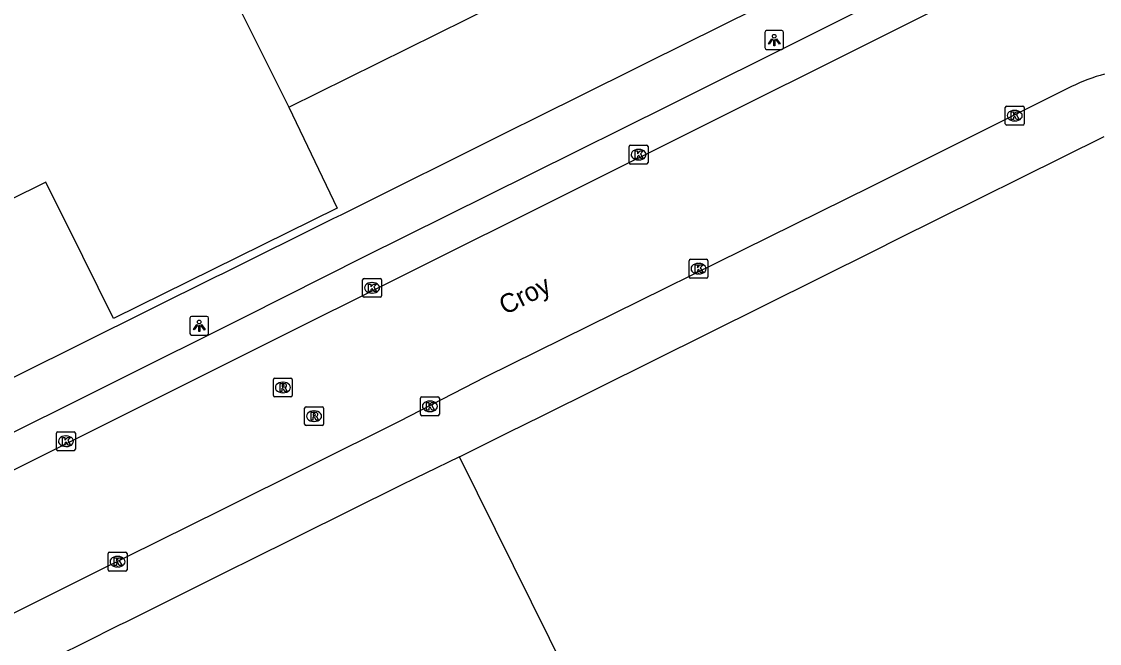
# Model space of a CAD drawing. Extents: x 157793 to 159380, y 380882 to 382313.
# Drawn here: x 157996.8 to 158053.9, y 381465.3 to 381498.3 of the extents above; entities that cross this region are included whole.
import ezdxf

# ---------------------------------------------------------------- set-up
doc = ezdxf.new("R2010")
doc.units = 0
for name, color, linetype in [('IMGEO_Kolk', 7, 'Continuous'), ('IMGEO_Lichtpunt', 7, 'Continuous'), ('IMGEO_Openbare_ruimte_label', 7, 'Continuous'), ('IMGEO_Pand', 7, 'Continuous'), ('IMGEO_Rijbaan_lokaal_gesloten', 7, 'Continuous'), ('IMGEO_Rioolput', 7, 'Continuous'), ('IMGEO_Voetpad_open', 7, 'Continuous')]:
    doc.layers.add(name, color=color, linetype=linetype)

msp = doc.modelspace()

# ---------------------------------------------------------------- linework, layer by layer
at = {"layer": 'IMGEO_Kolk'}
for p, q in [((158049.015, 381493.811), (158049.867, 381493.811)), ((158048.94, 381492.885), (158048.94, 381493.737)), ((158049.428, 381493.591), (158049.453, 381493.591)), ((158049.941, 381493.737), (158049.941, 381492.885)), ((158049.867, 381492.811), (158049.015, 381492.811)), ((158049.451, 381493.031), (158049.426, 381493.031)), ((158028.989, 381490.818), (158028.989, 381491.67)), ((158029.064, 381491.744), (158029.916, 381491.744)), ((158029.477, 381491.524), (158029.502, 381491.524)), ((158029.99, 381491.67), (158029.99, 381490.818)), ((158029.5, 381490.964), (158029.475, 381490.964)), ((158029.916, 381490.744), (158029.064, 381490.744)), ((158032.168, 381484.765), (158032.168, 381485.617)), ((158032.243, 381485.691), (158033.095, 381485.691)), ((158032.656, 381485.471), (158032.681, 381485.471)), ((158033.169, 381485.617), (158033.169, 381484.765)), ((158014.921, 381484.676), (158015.773, 381484.676)), ((158033.095, 381484.691), (158032.243, 381484.691)), ((158032.679, 381484.911), (158032.654, 381484.911)), ((158014.846, 381483.75), (158014.846, 381484.602)), ((158015.334, 381484.456), (158015.359, 381484.456)), ((158015.847, 381484.602), (158015.847, 381483.75)), ((158015.773, 381483.676), (158014.921, 381483.676)), ((158015.357, 381483.896), (158015.332, 381483.896)), ((158017.993, 381478.394), (158018.845, 381478.394)), ((158017.918, 381477.468), (158017.918, 381478.32)), ((158018.406, 381478.174), (158018.431, 381478.174)), ((158018.919, 381478.32), (158018.919, 381477.468)), ((158018.845, 381477.394), (158017.993, 381477.394)), ((158018.429, 381477.614), (158018.404, 381477.614)), ((157998.608, 381475.613), (157998.608, 381476.465)), ((157998.683, 381476.539), (157999.535, 381476.539)), ((157999.096, 381476.319), (157999.121, 381476.319)), ((157999.609, 381476.465), (157999.609, 381475.613)), ((157999.535, 381475.539), (157998.683, 381475.539)), ((157999.119, 381475.759), (157999.094, 381475.759)), ((158001.346, 381469.226), (158001.346, 381470.078)), ((158001.421, 381470.152), (158002.273, 381470.152)), ((158001.834, 381469.932), (158001.859, 381469.932)), ((158002.347, 381470.078), (158002.347, 381469.226)), ((158001.857, 381469.372), (158001.832, 381469.372)), ((158002.273, 381469.152), (158001.421, 381469.152))]:
    msp.add_line(p, q, dxfattribs=at)
for points in [[(158049.015, 381493.811), (158049.867, 381493.811)], [(158048.94, 381492.885), (158048.94, 381493.737)], [(158049.261, 381493.511), (158049.384, 381493.511), (158049.384, 381493.36), (158049.514, 381493.511), (158049.678, 381493.511), (158049.532, 381493.36), (158049.685, 381493.111), (158049.533, 381493.111), (158049.448, 381493.275), (158049.384, 381493.208), (158049.384, 381493.111), (158049.261, 381493.111), (158049.261, 381493.511)], [(158049.941, 381493.737), (158049.941, 381492.885)], [(158049.867, 381492.811), (158049.015, 381492.811)], [(158028.989, 381490.818), (158028.989, 381491.67)], [(158029.064, 381491.744), (158029.916, 381491.744)], [(158029.99, 381491.67), (158029.99, 381490.818)], [(158029.31, 381491.444), (158029.433, 381491.444), (158029.433, 381491.293), (158029.563, 381491.444), (158029.727, 381491.444), (158029.581, 381491.293), (158029.734, 381491.044), (158029.582, 381491.044), (158029.497, 381491.208), (158029.433, 381491.141), (158029.433, 381491.044), (158029.31, 381491.044), (158029.31, 381491.444)], [(158029.916, 381490.744), (158029.064, 381490.744)], [(158032.168, 381484.765), (158032.168, 381485.617)], [(158032.243, 381485.691), (158033.095, 381485.691)], [(158032.489, 381485.391), (158032.612, 381485.391), (158032.612, 381485.24), (158032.742, 381485.391), (158032.906, 381485.391), (158032.76, 381485.24), (158032.913, 381484.991), (158032.761, 381484.991), (158032.676, 381485.155), (158032.612, 381485.088), (158032.612, 381484.991), (158032.489, 381484.991), (158032.489, 381485.391)], [(158033.169, 381485.617), (158033.169, 381484.765)], [(158014.921, 381484.676), (158015.773, 381484.676)], [(158033.095, 381484.691), (158032.243, 381484.691)], [(158014.846, 381483.75), (158014.846, 381484.602)], [(158015.167, 381484.376), (158015.29, 381484.376), (158015.29, 381484.225), (158015.42, 381484.376), (158015.584, 381484.376), (158015.438, 381484.225), (158015.591, 381483.976), (158015.439, 381483.976), (158015.354, 381484.14), (158015.29, 381484.073), (158015.29, 381483.976), (158015.167, 381483.976), (158015.167, 381484.376)], [(158015.847, 381484.602), (158015.847, 381483.75)], [(158015.773, 381483.676), (158014.921, 381483.676)], [(158017.993, 381478.394), (158018.845, 381478.394)], [(158017.918, 381477.468), (158017.918, 381478.32)], [(158018.239, 381478.094), (158018.362, 381478.094), (158018.362, 381477.943), (158018.492, 381478.094), (158018.656, 381478.094), (158018.51, 381477.943), (158018.663, 381477.694), (158018.511, 381477.694), (158018.426, 381477.858), (158018.362, 381477.791), (158018.362, 381477.694), (158018.239, 381477.694), (158018.239, 381478.094)], [(158018.919, 381478.32), (158018.919, 381477.468)], [(158018.845, 381477.394), (158017.993, 381477.394)], [(157998.608, 381475.613), (157998.608, 381476.465)], [(157998.683, 381476.539), (157999.535, 381476.539)], [(157998.929, 381476.239), (157999.052, 381476.239), (157999.052, 381476.088), (157999.182, 381476.239), (157999.346, 381476.239), (157999.2, 381476.088), (157999.353, 381475.839), (157999.201, 381475.839), (157999.116, 381476.003), (157999.052, 381475.936), (157999.052, 381475.839), (157998.929, 381475.839), (157998.929, 381476.239)], [(157999.609, 381476.465), (157999.609, 381475.613)], [(157999.535, 381475.539), (157998.683, 381475.539)], [(158001.346, 381469.226), (158001.346, 381470.078)], [(158001.421, 381470.152), (158002.273, 381470.152)], [(158001.667, 381469.852), (158001.79, 381469.852), (158001.79, 381469.701), (158001.92, 381469.852), (158002.084, 381469.852), (158001.938, 381469.701), (158002.091, 381469.452), (158001.939, 381469.452), (158001.854, 381469.616), (158001.79, 381469.549), (158001.79, 381469.452), (158001.667, 381469.452), (158001.667, 381469.852)], [(158002.347, 381470.078), (158002.347, 381469.226)], [(158002.273, 381469.152), (158001.421, 381469.152)]]:
    msp.add_lwpolyline(points, dxfattribs=at)
for centre, start, end in [((158049.017, 381493.735), 91.552, 178.448), ((158049.017, 381493.735), 91.552, 178.448), ((158049.865, 381493.735), 1.552, 88.448), ((158049.865, 381493.735), 1.552, 88.448), ((158049.017, 381492.887), 181.552, 268.448), ((158049.017, 381492.887), 181.552, 268.448), ((158049.865, 381492.887), 271.552, 358.448), ((158049.865, 381492.887), 271.552, 358.448), ((158029.066, 381491.668), 91.552, 178.448), ((158029.066, 381491.668), 91.552, 178.448), ((158029.914, 381491.668), 1.552, 88.448), ((158029.914, 381491.668), 1.552, 88.448), ((158029.066, 381490.82), 181.552, 268.448), ((158029.066, 381490.82), 181.552, 268.448), ((158029.914, 381490.82), 271.552, 358.448), ((158029.914, 381490.82), 271.552, 358.448), ((158032.245, 381485.615), 91.552, 178.448), ((158032.245, 381485.615), 91.552, 178.448), ((158033.093, 381485.615), 1.552, 88.448), ((158033.093, 381485.615), 1.552, 88.448), ((158014.923, 381484.6), 91.552, 178.448), ((158014.923, 381484.6), 91.552, 178.448), ((158015.771, 381484.6), 1.552, 88.448), ((158015.771, 381484.6), 1.552, 88.448), ((158032.245, 381484.767), 181.552, 268.448), ((158032.245, 381484.767), 181.552, 268.448), ((158033.093, 381484.767), 271.552, 358.448), ((158033.093, 381484.767), 271.552, 358.448), ((158014.923, 381483.752), 181.552, 268.448), ((158014.923, 381483.752), 181.552, 268.448), ((158015.771, 381483.752), 271.552, 358.448), ((158015.771, 381483.752), 271.552, 358.448), ((158017.995, 381478.318), 91.552, 178.448), ((158017.995, 381478.318), 91.552, 178.448), ((158018.843, 381478.318), 1.552, 88.448), ((158018.843, 381478.318), 1.552, 88.448), ((158017.995, 381477.47), 181.552, 268.448), ((158017.995, 381477.47), 181.552, 268.448), ((158018.843, 381477.47), 271.552, 358.448), ((158018.843, 381477.47), 271.552, 358.448), ((157998.685, 381476.463), 91.552, 178.448), ((157998.685, 381476.463), 91.552, 178.448), ((157999.533, 381476.463), 1.552, 88.448), ((157999.533, 381476.463), 1.552, 88.448), ((157998.685, 381475.615), 181.552, 268.448), ((157998.685, 381475.615), 181.552, 268.448), ((157999.533, 381475.615), 271.552, 358.448), ((157999.533, 381475.615), 271.552, 358.448), ((158001.423, 381470.076), 91.552, 178.448), ((158001.423, 381470.076), 91.552, 178.448), ((158002.271, 381470.076), 1.552, 88.448), ((158002.271, 381470.076), 1.552, 88.448), ((158001.423, 381469.228), 181.552, 268.448), ((158001.423, 381469.228), 181.552, 268.448), ((158002.271, 381469.228), 271.552, 358.448), ((158002.271, 381469.228), 271.552, 358.448)]:
    msp.add_arc(centre, 0.0765, start, end, dxfattribs=at)
for centre, major_axis, ratio, start_param, end_param in [((158049.427, 381493.311), (-0.387, 0.002), 0.722429, 4.712389, 7.853982), ((158049.452, 381493.311), (-0.39, 0.002), 0.717154, 1.570796, 4.712389), ((158029.476, 381491.244), (-0.387, 0.002), 0.722429, 4.712389, 7.853982), ((158029.501, 381491.244), (-0.39, 0.002), 0.717154, 1.570796, 4.712389), ((158032.655, 381485.191), (-0.387, 0.002), 0.722429, 4.712389, 7.853982), ((158032.68, 381485.191), (-0.39, 0.002), 0.717154, 1.570796, 4.712389), ((158015.333, 381484.176), (-0.387, 0.002), 0.722429, 4.712389, 7.853982), ((158015.358, 381484.176), (-0.39, 0.002), 0.717154, 1.570796, 4.712389), ((158018.405, 381477.894), (-0.387, 0.002), 0.722429, 4.712389, 7.853982), ((158018.43, 381477.894), (-0.39, 0.002), 0.717154, 1.570796, 4.712389), ((157999.095, 381476.039), (-0.387, 0.002), 0.722429, 4.712389, 7.853982), ((157999.12, 381476.039), (-0.39, 0.002), 0.717154, 1.570796, 4.712389), ((158001.833, 381469.652), (-0.387, 0.002), 0.722429, 4.712389, 7.853982), ((158001.858, 381469.652), (-0.39, 0.002), 0.717154, 1.570796, 4.712389)]:
    msp.add_ellipse(centre, major_axis=major_axis, ratio=ratio, start_param=start_param, end_param=end_param, dxfattribs=at)
at = {"layer": 'IMGEO_Lichtpunt'}
for p, q in [((158037.087, 381497.82), (158036.279, 381497.82)), ((158037.087, 381497.82), (158036.279, 381497.82)), ((158036.185, 381497.725), (158036.185, 381496.918)), ((158036.185, 381497.725), (158036.185, 381496.918)), ((158037.181, 381496.918), (158037.181, 381497.725)), ((158037.181, 381496.918), (158037.181, 381497.725)), ((158036.279, 381496.824), (158037.087, 381496.824)), ((158036.279, 381496.824), (158037.087, 381496.824)), ((158005.68, 381482.567), (158005.68, 381481.76)), ((158005.68, 381482.567), (158005.68, 381481.76)), ((158006.582, 381482.662), (158005.774, 381482.662)), ((158006.582, 381482.662), (158005.774, 381482.662)), ((158006.676, 381481.76), (158006.676, 381482.567)), ((158006.676, 381481.76), (158006.676, 381482.567)), ((158005.774, 381481.666), (158006.582, 381481.666)), ((158005.774, 381481.666), (158006.582, 381481.666))]:
    msp.add_line(p, q, dxfattribs=at)
for points in [[(158036.559, 381497.389), (158036.598, 381497.361), (158036.41, 381497.099), (158036.372, 381497.126), (158036.559, 381497.389)], [(158036.661, 381497.341), (158036.708, 381497.341), (158036.708, 381497.019), (158036.661, 381497.019), (158036.661, 381497.341)], [(158036.771, 381497.361), (158036.809, 381497.388), (158036.996, 381497.126), (158036.957, 381497.098), (158036.771, 381497.361)], [(158006.054, 381482.231), (158006.093, 381482.203), (158005.905, 381481.941), (158005.867, 381481.968), (158006.054, 381482.231)], [(158006.156, 381482.183), (158006.203, 381482.183), (158006.203, 381481.861), (158006.156, 381481.861), (158006.156, 381482.183)], [(158006.266, 381482.203), (158006.304, 381482.23), (158006.491, 381481.968), (158006.452, 381481.94), (158006.266, 381482.203)]]:
    msp.add_lwpolyline(points, dxfattribs=at)
for centre in [(158036.684, 381497.523), (158006.179, 381482.365)]:
    msp.add_circle(centre, 0.0994, dxfattribs=at)
for centre, start, end in [((158036.279, 381497.725), 90, 180), ((158036.279, 381497.725), 90, 180), ((158037.087, 381497.725), 0, 90), ((158037.087, 381497.725), 0, 90), ((158036.279, 381496.918), 180, 270), ((158036.279, 381496.918), 180, 270), ((158037.087, 381496.918), 270, 0), ((158037.087, 381496.918), 270, 360), ((158005.774, 381482.567), 90, 180), ((158005.774, 381482.567), 90, 180), ((158006.582, 381482.567), 0, 90), ((158006.582, 381482.567), 0, 90), ((158005.774, 381481.76), 180, 270), ((158005.774, 381481.76), 180, 270), ((158006.582, 381481.76), 270, 0), ((158006.582, 381481.76), 270, 360)]:
    msp.add_arc(centre, 0.0946, start, end, dxfattribs=at)
at = {"layer": 'IMGEO_Pand'}
for points in [[(157999.625, 381516.436), (158007.818, 381500), (158010.931, 381493.756)], [(158010.931, 381493.756), (158023.52, 381500), (158034.984, 381505.686), (158036.664, 381502.3), (158038.334, 381501.747), (158046.251, 381505.681), (158048.555, 381512.439)], [(158010.931, 381493.756), (158013.496, 381488.404), (158001.635, 381482.543), (158000, 381485.833), (157998.036, 381489.785), (157982.493, 381482.086), (157986.075, 381474.845), (157974.596, 381469.163), (157974.788, 381468.773), (157974.352, 381468.563), (157960.246, 381496.977)], [(158019.981, 381475.214), (158022.566, 381476.498), (158024.363, 381477.391), (158042.053, 381486.177), (158043.211, 381486.752), (158054.194, 381492.208)], [(158027.635, 381459.625), (158027.622, 381459.792), (158019.981, 381475.214)]]:
    msp.add_lwpolyline(points, dxfattribs=at)
at = {"layer": 'IMGEO_Rijbaan_lokaal_gesloten'}
for points in [[(157978.347, 381465.538), (158009.399, 381481.054), (158049.371, 381501.011)], [(158052.459, 381494.851), (158041.845, 381489.551), (158021.34, 381479.433), (158016.78, 381477.087), (158007.384, 381472.404), (158000.654, 381469.071), (157991.736, 381464.625), (157980.176, 381458.897), (157976.095, 381456.733)]]:
    msp.add_lwpolyline(points, dxfattribs=at)
msp.add_arc((158056.31, 381487.245), 8.525, 104.284, 116.8569, dxfattribs=at)
at = {"layer": 'IMGEO_Rioolput'}
for p, q in [((158010.116, 381478.467), (158010.116, 381479.319)), ((158010.191, 381479.393), (158011.043, 381479.393)), ((158010.604, 381479.173), (158010.629, 381479.173)), ((158011.117, 381479.319), (158011.117, 381478.467)), ((158011.043, 381478.393), (158010.191, 381478.393)), ((158010.627, 381478.613), (158010.602, 381478.613)), ((158011.77, 381476.944), (158011.77, 381477.796)), ((158011.845, 381477.87), (158012.697, 381477.87)), ((158012.771, 381477.796), (158012.771, 381476.944)), ((158012.258, 381477.65), (158012.283, 381477.65)), ((158012.697, 381476.87), (158011.845, 381476.87)), ((158012.281, 381477.09), (158012.256, 381477.09))]:
    msp.add_line(p, q, dxfattribs=at)
for points in [[(158010.116, 381478.467), (158010.116, 381479.319)], [(158010.191, 381479.393), (158011.043, 381479.393)], [(158010.705, 381479.091), (158010.453, 381479.093), (158010.453, 381478.693)], [(158010.631, 381479.012), (158010.577, 381479.012), (158010.577, 381478.931)], [(158010.577, 381478.931), (158010.629, 381478.931)], [(158011.117, 381479.319), (158011.117, 381478.467)], [(158011.043, 381478.393), (158010.191, 381478.393)], [(158010.453, 381478.693), (158010.577, 381478.693), (158010.577, 381478.855), (158010.588, 381478.855)], [(158010.635, 381478.826), (158010.706, 381478.693), (158010.846, 381478.693), (158010.781, 381478.819)], [(158011.77, 381476.944), (158011.77, 381477.796)], [(158011.845, 381477.87), (158012.697, 381477.87)], [(158012.771, 381477.796), (158012.771, 381476.944)], [(158012.359, 381477.568), (158012.107, 381477.57), (158012.107, 381477.17)], [(158012.107, 381477.17), (158012.231, 381477.17), (158012.231, 381477.332), (158012.242, 381477.332)], [(158012.285, 381477.489), (158012.231, 381477.489), (158012.231, 381477.408)], [(158012.231, 381477.408), (158012.283, 381477.408)], [(158012.289, 381477.303), (158012.36, 381477.17), (158012.5, 381477.17), (158012.435, 381477.296)], [(158012.697, 381476.87), (158011.845, 381476.87)]]:
    msp.add_lwpolyline(points, dxfattribs=at)
for centre, radius, start, end in [((158010.193, 381479.317), 0.0765, 91.552, 178.448), ((158010.193, 381479.317), 0.0765, 91.552, 178.448), ((158010.613, 381479.12), 0.19, 274.7715, 282.9687), ((158010.637, 381478.916), 0.0964, 77.0061, 93.1865), ((158010.651, 381478.973), 0.0378, 276.6634, 79.6772), ((158010.704, 381478.981), 0.109, 350.3612, 89.416), ((158010.702, 381478.981), 0.112, 277.5842, 350.9817), ((158011.041, 381479.317), 0.0765, 1.552, 88.448), ((158011.041, 381479.317), 0.0765, 1.552, 88.448), ((158010.193, 381478.469), 0.0765, 181.552, 268.448), ((158010.193, 381478.469), 0.0765, 181.552, 268.448), ((158010.587, 381478.802), 0.0533, 26.0293, 88.6989), ((158010.686, 381478.766), 0.108, 29.5134, 73.7905), ((158011.041, 381478.469), 0.0765, 271.552, 358.448), ((158011.041, 381478.469), 0.0765, 271.552, 358.448), ((158011.847, 381477.794), 0.0765, 91.552, 178.448), ((158011.847, 381477.794), 0.0765, 91.552, 178.448), ((158012.695, 381477.794), 0.0765, 1.552, 88.448), ((158012.695, 381477.794), 0.0765, 1.552, 88.448), ((158012.241, 381477.279), 0.0533, 26.0293, 88.6989), ((158012.267, 381477.597), 0.19, 274.7715, 282.9687), ((158012.291, 381477.393), 0.0964, 77.0061, 93.1865), ((158012.305, 381477.45), 0.0378, 276.6634, 79.6772), ((158012.358, 381477.458), 0.109, 350.3612, 89.416), ((158012.356, 381477.458), 0.112, 277.5842, 350.9817), ((158012.34, 381477.243), 0.108, 29.5134, 73.7905), ((158011.847, 381476.946), 0.0765, 181.552, 268.448), ((158011.847, 381476.946), 0.0765, 181.552, 268.448), ((158012.695, 381476.946), 0.0765, 271.552, 358.448), ((158012.695, 381476.946), 0.0765, 271.552, 358.448)]:
    msp.add_arc(centre, radius, start, end, dxfattribs=at)
for centre, major_axis, ratio, start_param, end_param in [((158010.603, 381478.893), (-0.387, 0.002), 0.722429, 4.712389, 7.853982), ((158010.628, 381478.893), (-0.39, 0.002), 0.717154, 1.570796, 4.712389), ((158012.257, 381477.37), (-0.387, 0.002), 0.722429, 4.712389, 7.853982), ((158012.282, 381477.37), (-0.39, 0.002), 0.717154, 1.570796, 4.712389)]:
    msp.add_ellipse(centre, major_axis=major_axis, ratio=ratio, start_param=start_param, end_param=end_param, dxfattribs=at)
at = {"layer": 'IMGEO_Voetpad_open'}
for points in [[(157972.984, 381468.428), (157973.217, 381467.945), (158000, 381481.251), (158007.083, 381484.77), (158007.424, 381484.939), (158013.289, 381487.853), (158013.735, 381488.075), (158022.606, 381492.481), (158024.099, 381493.223), (158029.2, 381495.754), (158029.94, 381496.123), (158037.715, 381500), (158051.36, 381506.804)], [(158045.92, 381501.251), (158031.118, 381493.851), (158023.762, 381490.206), (158014.89, 381485.807), (158008.621, 381482.645), (157980.273, 381468.509)], [(158019.981, 381475.214), (158018.159, 381474.325), (158017.68, 381474.092), (158016.82, 381473.672), (158008.741, 381469.656), (158007.951, 381469.263), (158002.249, 381466.432), (158001.969, 381466.293), (158000, 381465.316), (157996.346, 381463.5), (157993.12, 381461.891), (157981.69, 381456.19)]]:
    msp.add_lwpolyline(points, dxfattribs=at)

# ---------------------------------------------------------------- texts
at = {"layer": 'IMGEO_Openbare_ruimte_label'}
msp.add_text('Croy', height=1, rotation=26.5394, dxfattribs=at).set_placement((158022.4, 381482.721))

doc.saveas('drawing.dxf')
